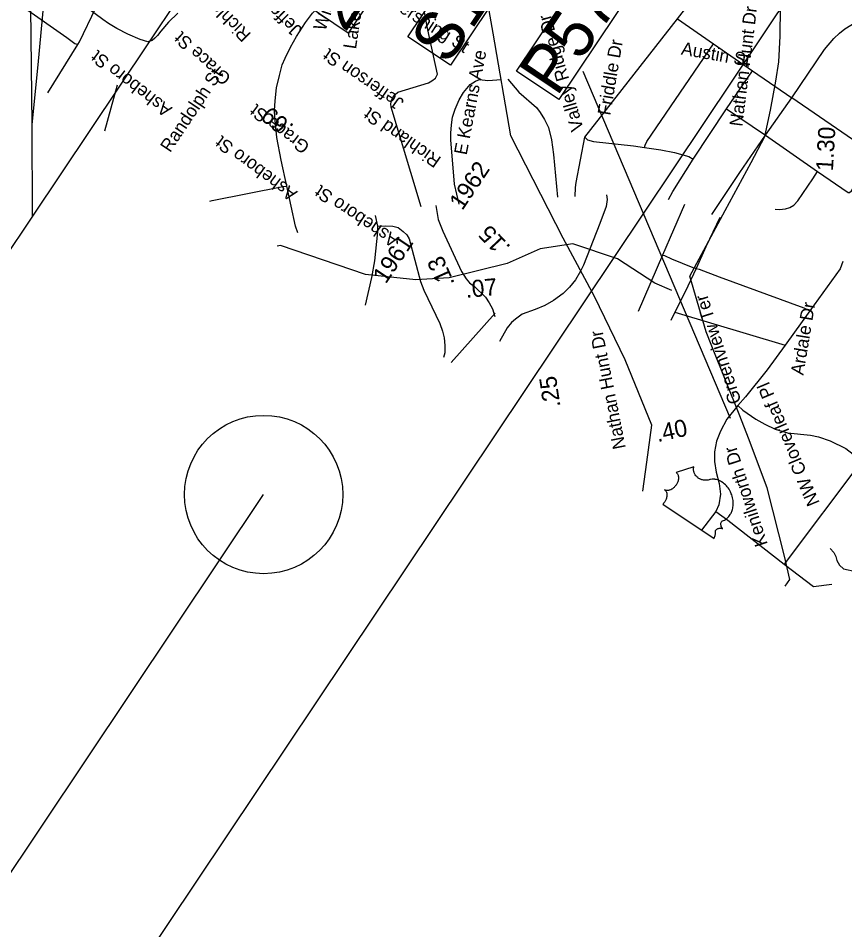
# Model space of a CAD drawing. Extents: x 1716282 to 1717158, y 799307 to 801078.
# Drawn here: x 1716840.6 to 1716928.3, y 800636.9 to 800733.7 of the extents above; entities that cross this region are included whole.
import ezdxf

# ---------------------------------------------------------------- set-up
doc = ezdxf.new("R2010")
doc.units = 0
for name, color, linetype in [('Exist Hydrographic Misc Water Feature', 7, 'Continuous'), ('Exist Road Non-System Type 51', 7, 'Continuous'), ('Exist Road Non-System Type 51 Label', 7, 'Continuous'), ('Exist Road Primary Interstate Divided Center Attributed', 7, 'Continuous'), ('Exist Road Primary Interstate Mileage Hundredths English Label', 7, 'Continuous'), ('Exist Road Primary Interstate Ramp 1 Lane Attributed', 7, 'Continuous'), ('Exist Road Primary Interstate Structure Ovrhead Sign CELL', 7, 'Continuous'), ('Exist Road Primary US Mileage Hundredths English Label', 7, 'Continuous'), ('Exist Road Primary US Shield CELL', 7, 'Continuous'), ('Exist Road Primary US Structure Pipe Number Label', 7, 'Continuous'), ('Exist Road Primary US Structure Standard Bridge Number Label', 7, 'Continuous'), ('Exist Road Secondary Mileage Hundredths English Label', 7, 'Continuous'), ('Exist Road Secondary Mileage Tenths English Label', 7, 'Continuous'), ('Exist Road Secondary Type 51 Number Label', 7, 'Continuous'), ('Exist Utilities Electrical Transmission Line', 7, 'Continuous'), ('Prop DSN Text', 7, 'Continuous')]:
    doc.layers.add(name, color=color, linetype=linetype)

msp = doc.modelspace()

# ---------------------------------------------------------------- linework, layer by layer
at = {"layer": 'Exist Hydrographic Misc Water Feature'}
for points in [[(1716857.569, 800734.207), (1716856.583, 800733.23), (1716855.76, 800732.281), (1716855.409, 800731.819), (1716855.108, 800731.532), (1716854.84, 800731.294), (1716854.364, 800731.163), (1716853.569, 800731.388), (1716852.248, 800731.975), (1716851.096, 800732.55), (1716850.202, 800733.093), (1716849.603, 800733.503), (1716847.321, 800735.2)], [(1716910.003, 800704.752), (1716908.183, 800705.552), (1716904.225, 800708.113), (1716899.491, 800709.729), (1716896.023, 800709.172), (1716892.501, 800707.62), (1716886.343, 800706.123), (1716882.82, 800705.9), (1716877.475, 800706.476), (1716868.477, 800709.55), (1716868.095, 800709.477)], [(1716926.789, 800677.403), (1716927.187, 800676.956), (1716927.392, 800676.536), (1716927.491, 800676.115), (1716927.791, 800675.63), (1716928.22, 800675.23), (1716929.53, 800674.935)]]:
    msp.add_lwpolyline(points, dxfattribs=at)
at = {"layer": 'Exist Road Non-System Type 51'}
for p, q in [((1716900.758, 800721.045), (1716910.573, 800733.603)), ((1716910.573, 800733.603), (1716914.396, 800730.93)), ((1716843.784, 800725.748), (1716846.943, 800730.852)), ((1716914.396, 800730.93), (1716918.539, 800728.083)), ((1716915.79, 800724.043), (1716918.539, 800728.083)), ((1716918.539, 800728.083), (1716922.727, 800725.212)), ((1716849.808, 800721.716), (1716851.176, 800726.593)), ((1716919.922, 800721.234), (1716922.727, 800725.212)), ((1716912.247, 800718.709), (1716915.79, 800724.043)), ((1716915.79, 800724.043), (1716919.922, 800721.234)), ((1716919.922, 800721.234), (1716925.455, 800717.382)), ((1716911.322, 800713.886), (1716909.011, 800708.524)), ((1716878.521, 800712.711), (1716878.77, 800711.578)), ((1716909.011, 800708.524), (1716906.419, 800702.542)), ((1716924.646, 800702.591), (1716922.011, 800698.965)), ((1716910.317, 800702.478), (1716909.881, 800701.586)), ((1716910.317, 800702.478), (1716922.011, 800698.965)), ((1716930.146, 800686.692), (1716921.919, 800675.727)), ((1716914.644, 800681.321), (1716913.12, 800679.341))]:
    msp.add_line(p, q, dxfattribs=at)
for points in [[(1716910.573, 800733.603), (1716914.462, 800738.624), (1716915.162, 800739.678), (1716916.114, 800741.139), (1716919.604, 800746.862), (1716921.123, 800749.398), (1716921.481, 800750.097)], [(1716837.134, 800737.677), (1716845.797, 800731.619), (1716846.644, 800730.987), (1716846.943, 800730.852)], [(1716922.727, 800725.212), (1716926.19, 800730.332), (1716927.184, 800731.494), (1716927.773, 800732.066), (1716928.347, 800732.528), (1716931.933, 800734.726), (1716932.599, 800735.384), (1716933.015, 800735.986), (1716933.71, 800737.292)], [(1716846.943, 800730.852), (1716847.142, 800731.144), (1716848.86, 800734.764), (1716849.352, 800736.204)], [(1716869.135, 800715.833), (1716868.519, 800718.609), (1716868.059, 800720.993), (1716867.85, 800723.144), (1716867.829, 800723.874), (1716867.884, 800724.886), (1716868.041, 800726.256), (1716868.341, 800727.592), (1716868.632, 800728.704), (1716868.938, 800729.409), (1716869.514, 800730.6), (1716870.141, 800731.727), (1716871.115, 800733.201), (1716871.849, 800734.189), (1716872.919, 800735.364), (1716873.65, 800736.011)], [(1716883.402, 800713.642), (1716880.208, 800724.23), (1716880.169, 800724.563), (1716880.238, 800724.964), (1716880.4, 800725.305), (1716880.629, 800725.57), (1716880.924, 800725.792), (1716884.179, 800726.815), (1716884.531, 800727.007), (1716884.915, 800727.28), (1716885.121, 800727.711), (1716884.089, 800732.43), (1716883.672, 800734.687)], [(1716907.101, 800719.936), (1716907.156, 800720.202), (1716907.348, 800720.559), (1716914.396, 800730.93)], [(1716887.429, 800713.938), (1716886.914, 800716.055), (1716886.548, 800720.765), (1716886.535, 800721.456), (1716886.596, 800722.327), (1716886.729, 800723.149), (1716886.993, 800724.02), (1716887.425, 800725.004), (1716887.877, 800725.775), (1716888.604, 800726.634), (1716889.146, 800726.993), (1716889.582, 800727.138), (1716890.447, 800727.062), (1716891.896, 800727.146)], [(1716892.576, 800727.19), (1716893.754, 800725.824), (1716895.616, 800724.166), (1716895.999, 800723.663), (1716896.458, 800722.919), (1716896.889, 800722.064), (1716897.201, 800720.738), (1716897.417, 800719.207), (1716897.849, 800714.658)], [(1716925.455, 800717.382), (1716928.696, 800715.159), (1716928.835, 800715.181), (1716929.05, 800715.343), (1716930.874, 800718.082), (1716930.966, 800718.357), (1716931.012, 800718.788), (1716930.899, 800719.298), (1716930.669, 800719.701), (1716930.396, 800719.955), (1716922.727, 800725.212)], [(1716899.745, 800714.748), (1716899.747, 800715.708), (1716899.825, 800716.229), (1716900.758, 800721.045)], [(1716900.758, 800721.045), (1716901.023, 800720.749), (1716901.669, 800720.572), (1716905.904, 800720.111), (1716907.101, 800719.936)], [(1716914.235, 800712.839), (1716917.196, 800717.292), (1716919.922, 800721.234)], [(1716907.101, 800719.936), (1716908.802, 800719.708), (1716910.275, 800719.409), (1716911.797, 800718.995), (1716912.247, 800718.709)], [(1716909.627, 800714.432), (1716910.078, 800715.282), (1716912.247, 800718.709)], [(1716920.94, 800713.403), (1716921.402, 800713.373), (1716922.062, 800713.42), (1716922.51, 800713.565), (1716922.95, 800713.812), (1716923.346, 800714.275), (1716924.966, 800716.611), (1716925.455, 800717.382)], [(1716860.952, 800714.258), (1716861.216, 800714.3), (1716868.691, 800715.801), (1716869.135, 800715.833)], [(1716870.29, 800710.874), (1716870.062, 800711.609), (1716869.135, 800715.833)], [(1716903.039, 800714.907), (1716903.115, 800714.433), (1716903.018, 800713.68), (1716902.361, 800711.889), (1716900.619, 800707.458), (1716900.295, 800706.811), (1716899.75, 800705.894), (1716899.132, 800705.13), (1716898.462, 800704.457), (1716897.434, 800703.701), (1716896.508, 800703.18), (1716895.498, 800702.744), (1716894.104, 800702.261), (1716893.403, 800701.736), (1716892.977, 800701.367), (1716892.504, 800700.796), (1716891.717, 800699.366)], [(1716884.958, 800713.77), (1716885.208, 800712.288), (1716885.7, 800711.066), (1716887.68, 800706.773), (1716888.162, 800706.001), (1716888.532, 800705.57), (1716889.039, 800705.198), (1716890.202, 800704.062), (1716890.611, 800703.474), (1716890.942, 800702.821), (1716891.195, 800702.001)], [(1716915.089, 800712.521), (1716913.61, 800709.394), (1716912.554, 800707.099)], [(1716878.77, 800711.578), (1716878.742, 800710.982), (1716878.424, 800707.901), (1716878.109, 800706.145), (1716877.434, 800703.226)], [(1716878.77, 800711.578), (1716879.643, 800711.63), (1716880.374, 800711.588), (1716880.958, 800711.44), (1716881.471, 800711.037), (1716881.859, 800710.678), (1716882.124, 800710.234), (1716883.327, 800705.71), (1716883.661, 800704.806), (1716885.356, 800701.261), (1716885.648, 800700.458), (1716885.81, 800699.73), (1716885.915, 800698.942), (1716885.891, 800698.155), (1716885.759, 800697.654)], [(1716909.011, 800708.524), (1716909.202, 800708.479), (1716909.964, 800708.123), (1716912.215, 800707.195), (1716912.554, 800707.099)], [(1716928.116, 800707.846), (1716927.866, 800707.082), (1716924.646, 800702.591)], [(1716912.554, 800707.099), (1716911.407, 800704.612), (1716910.317, 800702.478)], [(1716912.554, 800707.099), (1716912.886, 800707.021), (1716914.992, 800706.22), (1716923.995, 800702.94), (1716924.646, 800702.591)], [(1716922.011, 800698.965), (1716920.115, 800696.35), (1716917.793, 800693.49), (1716916.976, 800692.55)], [(1716916.976, 800692.55), (1716915.837, 800691.109), (1716915.138, 800689.832), (1716914.737, 800688.768), (1716914.528, 800687.654), (1716914.518, 800686.607), (1716914.703, 800685.508), (1716915.024, 800684.298), (1716915.139, 800683.168), (1716914.984, 800682.014), (1716914.644, 800681.321)], [(1716916.976, 800692.55), (1716917.535, 800692.079), (1716918.912, 800691.131), (1716919.845, 800690.583), (1716920.955, 800690.052), (1716922.244, 800689.664), (1716924.707, 800689.423), (1716925.54, 800689.225), (1716926.785, 800688.82), (1716928.443, 800688.015), (1716930.146, 800686.692)], [(1716914.644, 800681.321), (1716915.943, 800680.386), (1716921.919, 800675.727)], [(1716921.919, 800675.727), (1716925.006, 800673.353), (1716926.956, 800673.593)]]:
    msp.add_lwpolyline(points, dxfattribs=at)
at = {"layer": 'Exist Road Primary Interstate Divided Center Attributed'}
for points in [[(1716842.123, 800722.391), (1716841.779, 800750.268)], [(1716842.159, 800712.684), (1716842.123, 800722.391)]]:
    msp.add_lwpolyline(points, dxfattribs=at)
at = {"layer": 'Exist Road Primary Interstate Ramp 1 Lane Attributed'}
msp.add_lwpolyline([(1716842.123, 800722.391), (1716842.743, 800728.725), (1716843.511, 800737.112), (1716843.884, 800738.685), (1716844.748, 800741.237), (1716846.172, 800744.34), (1716848.375, 800748.853), (1716849.138, 800750.58), (1716849.466, 800751.502), (1716849.576, 800751.954), (1716849.661, 800752.476), (1716849.709, 800752.848), (1716849.678, 800753.525)], dxfattribs=at)
at = {"layer": 'Exist Road Primary Interstate Structure Ovrhead Sign CELL'}
msp.add_lwpolyline([(1716881.982, 800731.684), (1716894.725, 800750.723), (1716899.233, 800747.705), (1716886.49, 800728.666)], close=True, dxfattribs=at)
at = {"layer": 'Exist Road Primary US Shield CELL'}
msp.add_line((1716909.029, 800682.079), (1716914.464, 800678.442), dxfattribs=at)
msp.add_lwpolyline([(1716914.464, 800678.442), (1716914.486, 800678.49), (1716914.525, 800678.582), (1716914.557, 800678.674), (1716914.581, 800678.763), (1716914.599, 800678.841), (1716914.609, 800678.91), (1716914.619, 800679.006), (1716914.622, 800679.091), (1716914.621, 800679.171), (1716914.618, 800679.257), (1716914.637, 800679.306), (1716914.657, 800679.337), (1716914.685, 800679.373), (1716914.727, 800679.412), (1716914.767, 800679.44), (1716914.816, 800679.467), (1716914.881, 800679.498), (1716914.953, 800679.52), (1716915.018, 800679.534), (1716915.1, 800679.544), (1716915.159, 800679.546), (1716915.222, 800679.542), (1716915.291, 800679.53), (1716915.385, 800679.497), (1716915.331, 800679.554), (1716915.299, 800679.6), (1716915.276, 800679.638), (1716915.236, 800679.73), (1716915.224, 800679.771), (1716915.209, 800679.824), (1716915.197, 800679.896), (1716915.193, 800679.952), (1716915.193, 800680.02), (1716915.198, 800680.068), (1716915.214, 800680.143), (1716915.241, 800680.208), (1716915.285, 800680.267), (1716915.309, 800680.289), (1716915.363, 800680.318), (1716915.569, 800680.41), (1716915.678, 800680.473), (1716915.777, 800680.541), (1716915.875, 800680.623), (1716915.961, 800680.707), (1716916.037, 800680.791), (1716916.111, 800680.885), (1716916.178, 800680.985), (1716916.223, 800681.062), (1716916.267, 800681.144), (1716916.309, 800681.234), (1716916.341, 800681.312), (1716916.415, 800681.536), (1716916.448, 800681.678), (1716916.469, 800681.791), (1716916.485, 800681.924), (1716916.495, 800682.086), (1716916.496, 800682.257), (1716916.488, 800682.386), (1716916.479, 800682.48), (1716916.456, 800682.64), (1716916.431, 800682.768), (1716916.391, 800682.931), (1716916.345, 800683.076), (1716916.298, 800683.205), (1716916.253, 800683.312), (1716916.209, 800683.409), (1716916.13, 800683.559), (1716916.059, 800683.682), (1716915.952, 800683.838), (1716915.875, 800683.937), (1716915.783, 800684.047), (1716915.699, 800684.135), (1716915.553, 800684.271), (1716915.42, 800684.377), (1716915.271, 800684.476), (1716915.142, 800684.548), (1716915.074, 800684.581), (1716914.932, 800684.641), (1716914.866, 800684.663), (1716914.737, 800684.702), (1716914.598, 800684.73), (1716914.534, 800684.738), (1716914.459, 800684.744), (1716914.388, 800684.748), (1716914.317, 800684.748), (1716914.251, 800684.745), (1716914.104, 800684.727), (1716914.022, 800684.71), (1716913.956, 800684.693), (1716913.836, 800684.659), (1716913.746, 800684.642), (1716913.647, 800684.631), (1716913.483, 800684.632), (1716913.333, 800684.647), (1716913.245, 800684.666), (1716913.159, 800684.691), (1716913.087, 800684.716), (1716913.031, 800684.74), (1716912.967, 800684.768), (1716912.909, 800684.799), (1716912.851, 800684.834), (1716912.797, 800684.87), (1716912.745, 800684.911), (1716912.641, 800685.002), (1716912.594, 800685.051), (1716912.541, 800685.114), (1716912.465, 800685.222), (1716912.431, 800685.279), (1716912.396, 800685.349), (1716912.367, 800685.417), (1716912.341, 800685.488), (1716912.325, 800685.543), (1716912.311, 800685.603), (1716912.301, 800685.665), (1716912.292, 800685.725), (1716912.289, 800685.855), (1716912.293, 800685.932), (1716912.306, 800686.024), (1716912.314, 800686.062), (1716910.437, 800685.464), (1716910.474, 800685.438), (1716910.515, 800685.402), (1716910.558, 800685.355), (1716910.593, 800685.302), (1716910.624, 800685.249), (1716910.648, 800685.188), (1716910.674, 800685.094), (1716910.688, 800685.004), (1716910.695, 800684.931), (1716910.692, 800684.84), (1716910.68, 800684.733), (1716910.666, 800684.654), (1716910.644, 800684.568), (1716910.613, 800684.477), (1716910.587, 800684.41), (1716910.55, 800684.329), (1716910.514, 800684.259), (1716910.474, 800684.192), (1716910.429, 800684.122), (1716910.389, 800684.066), (1716910.337, 800684), (1716910.282, 800683.938), (1716910.226, 800683.879), (1716910.165, 800683.823), (1716910.102, 800683.771), (1716910.049, 800683.732), (1716909.994, 800683.696), (1716909.874, 800683.629), (1716909.756, 800683.582), (1716909.708, 800683.567), (1716909.651, 800683.554), (1716909.545, 800683.542), (1716909.48, 800683.542), (1716909.407, 800683.551), (1716909.358, 800683.562), (1716909.315, 800683.577), (1716909.274, 800683.595), (1716909.212, 800683.631), (1716909.279, 800683.578), (1716909.308, 800683.548), (1716909.367, 800683.469), (1716909.39, 800683.425), (1716909.413, 800683.377), (1716909.444, 800683.278), (1716909.464, 800683.166), (1716909.466, 800683.095), (1716909.465, 800683.007), (1716909.454, 800682.904), (1716909.437, 800682.815), (1716909.412, 800682.723), (1716909.385, 800682.644), (1716909.315, 800682.48), (1716909.237, 800682.342), (1716909.153, 800682.221), (1716909.057, 800682.107), (1716909.029, 800682.079)], dxfattribs=at)
at = {"layer": 'Exist Road Primary US Structure Pipe Number Label'}
msp.add_line((1716916.199, 800691.19), (1716900.593, 800727.989), dxfattribs=at)
msp.add_lwpolyline([(1716893.497, 800728.043), (1716903.574, 800743.099), (1716908.068, 800740.091), (1716897.991, 800725.035)], close=True, dxfattribs=at)
at = {"layer": 'Exist Road Primary US Structure Standard Bridge Number Label'}
msp.add_lwpolyline([(1716871.075, 800735.132), (1716880.977, 800749.925), (1716885.533, 800746.875), (1716875.632, 800732.082)], close=True, dxfattribs=at)
at = {"layer": 'Exist Road Secondary Type 51 Number Label'}
msp.add_line((1716891.225, 800702.36), (1716886.555, 800697.122), dxfattribs=at)
at = {"layer": 'Exist Utilities Electrical Transmission Line'}
for points in [[(1716906.924, 800683.488), (1716907.323, 800686.559), (1716907.877, 800690.473), (1716905.045, 800697.394), (1716901.769, 800704.126), (1716898.442, 800710.331), (1716892.895, 800721.165), (1716891.042, 800732.059), (1716889.678, 800739.724)], [(1716922.02, 800673.384), (1716922.523, 800674.103), (1716921.945, 800676.58), (1716920.091, 800683.844), (1716918.107, 800689.087), (1716917.191, 800691.48), (1716914.215, 800698.851), (1716913.621, 800700.392), (1716911.914, 800706.289), (1716915.634, 800713.263), (1716918.392, 800718.337), (1716919.869, 800721.089), (1716920.457, 800723.888), (1716921.039, 800726.971), (1716921.33, 800729.025), (1716921.466, 800731.735), (1716921.533, 800734.836)]]:
    msp.add_lwpolyline(points, dxfattribs=at)
at = {"layer": 'Prop DSN Text'}
msp.add_line((1716783.235, 800558.464), (1716866.668, 800683.12), dxfattribs=at)
for points in [[(1716644.267, 800417.02), (1716922.463, 800832.664), (1716560.178, 801075.146), (1716281.982, 800659.503)], [(1716644.267, 800417.02), (1716922.463, 800832.664), (1716967.08, 800802.801), (1716688.884, 800387.158)]]:
    msp.add_lwpolyline(points, close=True, dxfattribs=at)
msp.add_circle((1716866.668, 800683.12), 8.4, dxfattribs=at)

# ---------------------------------------------------------------- texts
at = {"layer": 'Exist Road Non-System Type 51 Label'}
for s, rotation, p in [('Jefferson St', 135.55183, (1716870.834, 800732.534)), ('Wise Ave', 71.4686, (1716873.211, 800732.22)), ('Richland St', 134.65144, (1716865.43, 800731.977)), ('Lake Ave', 81.56169, (1716876.468, 800730.326)), ('Pershing St', 327.41472, (1716879.916, 800735.053)), ('Nathan Hunt Dr', 82.87203, (1716917.46, 800722.118)), ('Valley Ridge Dr', 106.12958, (1716900.645, 800721.883)), ('Grace St', 137.40259, (1716863.312, 800727.425)), ('Friddle Dr', 80.39387, (1716903.448, 800723.286)), ('Austin St', 349.89143, (1716910.912, 800729.813)), ('Asheboro St', 142.24786, (1716857.048, 800724.14)), ('Jefferson St', 145.31381, (1716881.666, 800724.924)), ('E Kearns Ave', 79.20571, (1716888.211, 800719.078)), ('Randolph St', 56.20506, (1716856.745, 800719.327)), ('Grace St', 142.94811, (1716871.676, 800720.249)), ('Richland St', 144.76889, (1716885.612, 800718.821)), ('Asheboro St', 143.45944, (1716870.34, 800715.233)), ('Asheboro St', 146.20506, (1716881.122, 800710.384)), ('Greenview Ter', 107.7088, (1716917.384, 800692.963)), ('Ardale Dr', 80.58305, (1716923.94, 800695.725)), ('Nathan Hunt Dr', 101.22165, (1716905.111, 800688.07)), ('NW Cloverleaf Pl', 112.81248, (1716925.697, 800682.243)), ('Kenilworth Dr', 107.85984, (1716920.178, 800677.851))]:
    msp.add_text(s, height=1.3775, rotation=rotation, dxfattribs=at).set_placement(p)
at = {"layer": 'Exist Road Primary Interstate Mileage Hundredths English Label'}
msp.add_text('1.30', height=1.8125, rotation=86.63105, dxfattribs=at).set_placement((1716927.077, 800717.385))
at = {"layer": 'Exist Road Primary Interstate Structure Ovrhead Sign CELL'}
msp.add_text('S1068', height=5.075, rotation=56.20506, dxfattribs=at).set_placement((1716886.221, 800728.566))
at = {"layer": 'Exist Road Primary US Mileage Hundredths English Label'}
msp.add_text('.40', height=1.8125, rotation=12.41485, dxfattribs=at).set_placement((1716908.484, 800688.669))
at = {"layer": 'Exist Road Primary US Structure Pipe Number Label'}
msp.add_text('P575', height=5.075, rotation=56.20506, dxfattribs=at).set_placement((1716897.78, 800725.234))
at = {"layer": 'Exist Road Primary US Structure Standard Bridge Number Label'}
msp.add_text('2222', height=5.075, rotation=56.20506, dxfattribs=at).set_placement((1716875.315, 800732.04))
at = {"layer": 'Exist Road Secondary Mileage Hundredths English Label'}
msp.add_text('.07', height=1.8125, rotation=5.28181, dxfattribs=at).set_placement((1716888.163, 800703.975))
at = {"layer": 'Exist Road Secondary Mileage Tenths English Label'}
for s, rotation, p in [('.69', 140.27059, (1716869.98, 800722.254)), ('.15', 133.37829, (1716892.96, 800709.413)), ('.13', 114.06447, (1716886.981, 800705.52)), ('.25', 98.48899, (1716898.18, 800692.46))]:
    msp.add_text(s, height=1.8125, rotation=rotation, dxfattribs=at).set_placement(p)
at = {"layer": 'Exist Road Secondary Type 51 Number Label'}
for s, p in [('1962', (1716887.751, 800713.186)), ('1961', (1716879.636, 800705.386))]:
    msp.add_text(s, height=1.8125, rotation=56.20506, dxfattribs=at).set_placement(p)

doc.saveas('drawing.dxf')
